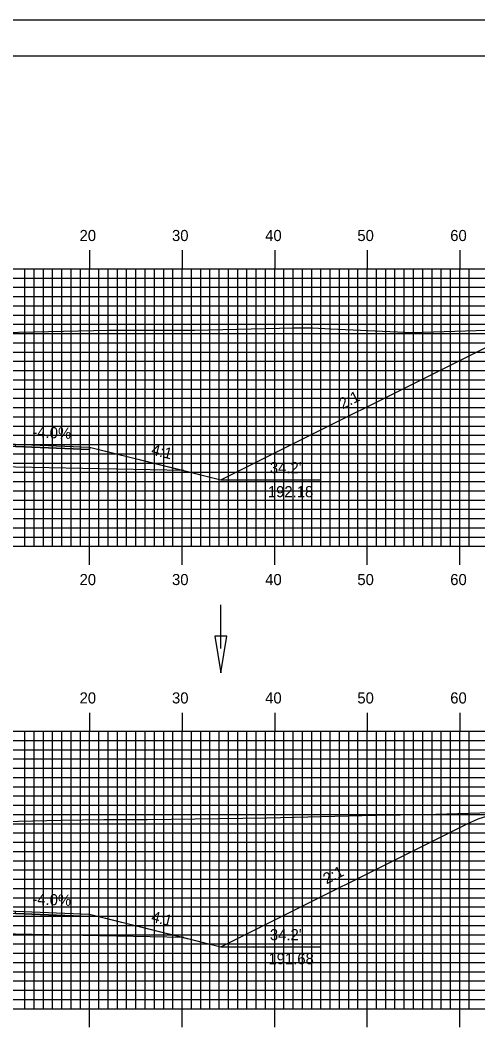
# Model space of a CAD drawing. Extents: x 1799568 to 1799912, y 442591 to 442811.
# Drawn here: x 1799746.5 to 1799796, y 442701.2 to 442810.5 of the extents above; entities that cross this region are included whole.
import ezdxf

# ---------------------------------------------------------------- set-up
doc = ezdxf.new("R2010")
doc.units = 0
for name, color, linetype in [('ANNOTATION', 7, 'Continuous'), ('BORDER', 7, 'Continuous'), ('D_Drainage_Ditch_Line', 7, 'Continuous'), ('D_Roadway_Centerline', 7, 'Continuous'), ('D_Roadway_Edge_Shoulder', 7, 'Continuous'), ('D_Roadway_SlopeLines', 7, 'Continuous'), ('D_Roadway_SubGrade', 7, 'Continuous'), ('H_V ANNOTATION', 7, 'Continuous'), ('MAJOR', 7, 'Continuous'), ('MINOR', 7, 'Continuous'), ('PDRAIN', 7, 'Continuous'), ('PLOT BOUNDARY', 7, 'Continuous'), ('S_Roadway_Centerline', 7, 'Continuous')]:
    doc.layers.add(name, color=color, linetype=linetype)

msp = doc.modelspace()

# ---------------------------------------------------------------- linework, layer by layer
at = {"layer": 'BORDER'}
msp.add_lwpolyline([(1799584.41, 442596.67), (1799904.41, 442596.67), (1799904.41, 442806.67), (1799584.41, 442806.67)], close=True, dxfattribs=at)
at = {"layer": 'D_Drainage_Ditch_Line'}
msp.add_line((1799768.18, 442742.63), (1799768.18, 442747.33), dxfattribs=at)
msp.add_lwpolyline([(1799768.84, 442743.94), (1799767.53, 442743.94), (1799768.18, 442740)], close=True, dxfattribs=at)
at = {"layer": 'D_Roadway_Centerline'}
for points in [[(1799669.45, 442775.1), (1799670.7, 442775.09), (1799671.95, 442774.91), (1799673.2, 442774.55), (1799674.45, 442774.02), (1799699.84, 442761.33), (1799703.84, 442762.33), (1799714.01, 442764.87), (1799722.01, 442765.19), (1799734.01, 442764.95), (1799746.01, 442764.71), (1799754.01, 442764.39), (1799764.18, 442761.85), (1799768.18, 442760.85), (1799798.21, 442775.86), (1799799.46, 442776.41), (1799800.71, 442776.8), (1799801.96, 442777.05), (1799803.21, 442777.14)], [(1799674.31, 442722.27), (1799675.56, 442722.22), (1799676.81, 442722.01), (1799678.06, 442721.63), (1799679.31, 442721.09), (1799699.84, 442710.83), (1799703.84, 442711.83), (1799714.01, 442714.37), (1799722.01, 442714.69), (1799734.01, 442714.45), (1799746.01, 442714.21), (1799754.01, 442713.89), (1799764.18, 442711.35), (1799768.18, 442710.35), (1799794.75, 442723.63), (1799796, 442724.18), (1799797.25, 442724.58), (1799798.5, 442724.84), (1799799.75, 442724.95)]]:
    msp.add_lwpolyline(points, dxfattribs=at)
at = {"layer": 'D_Roadway_Edge_Shoulder'}
for points in [[(1799746.01, 442764.71), (1799754.01, 442764.39), (1799754.01, 442764.14), (1799746.01, 442764.46)], [(1799746.01, 442714.21), (1799754.01, 442713.89), (1799754.01, 442713.64), (1799746.01, 442713.96)]]:
    msp.add_lwpolyline(points, close=True, dxfattribs=at)
at = {"layer": 'D_Roadway_SlopeLines'}
for points in [[(1799768.18, 442760.85), (1799798.21, 442775.86), (1799799.46, 442776.41), (1799800.71, 442776.8), (1799801.96, 442777.05), (1799803.21, 442777.14)], [(1799754.01, 442764.39), (1799768.18, 442760.85)], [(1799768.18, 442710.35), (1799794.75, 442723.63), (1799796, 442724.18), (1799797.25, 442724.58), (1799798.5, 442724.84), (1799799.75, 442724.95)], [(1799754.01, 442713.89), (1799768.18, 442710.35)]]:
    msp.add_lwpolyline(points, dxfattribs=at)
at = {"layer": 'D_Roadway_SubGrade'}
for points in [[(1799722.01, 442762.69), (1799703.84, 442762.33), (1799714.01, 442764.87), (1799714.01, 442764.62), (1799722.01, 442764.94), (1799734.01, 442764.7), (1799746.01, 442764.46), (1799754.01, 442764.14), (1799754.01, 442764.39), (1799764.18, 442761.85), (1799746.01, 442762.21), (1799734.01, 442762.45)], [(1799722.01, 442712.19), (1799703.84, 442711.83), (1799714.01, 442714.37), (1799714.01, 442714.12), (1799722.01, 442714.44), (1799734.01, 442714.2), (1799746.01, 442713.96), (1799754.01, 442713.64), (1799754.01, 442713.89), (1799764.18, 442711.35), (1799746.01, 442711.71), (1799734.01, 442711.95)]]:
    msp.add_lwpolyline(points, close=True, dxfattribs=at)
at = {"layer": 'MAJOR'}
for p, q in [((1799754.01, 442785.67), (1799754.01, 442783.67)), ((1799764.01, 442785.67), (1799764.01, 442783.67)), ((1799774.01, 442785.67), (1799774.01, 442783.67)), ((1799784.01, 442785.67), (1799784.01, 442783.67)), ((1799794.01, 442785.67), (1799794.01, 442783.67)), ((1799594.01, 442783.67), (1799874.01, 442783.67)), ((1799594.01, 442783.67), (1799874.01, 442783.67)), ((1799754.01, 442753.67), (1799754.01, 442783.67)), ((1799764.01, 442753.67), (1799764.01, 442783.67)), ((1799774.01, 442753.67), (1799774.01, 442783.67)), ((1799784.01, 442753.67), (1799784.01, 442783.67)), ((1799794.01, 442753.67), (1799794.01, 442783.67)), ((1799594.01, 442778.67), (1799874.01, 442778.67)), ((1799594.01, 442773.67), (1799874.01, 442773.67)), ((1799594.01, 442768.67), (1799874.01, 442768.67)), ((1799594.01, 442763.67), (1799874.01, 442763.67)), ((1799594.01, 442758.67), (1799874.01, 442758.67)), ((1799594.01, 442753.67), (1799874.01, 442753.67)), ((1799594.01, 442753.67), (1799874.01, 442753.67)), ((1799754.01, 442751.66), (1799754.01, 442753.67)), ((1799764.01, 442751.66), (1799764.01, 442753.67)), ((1799774.01, 442751.66), (1799774.01, 442753.67)), ((1799784.01, 442751.66), (1799784.01, 442753.67)), ((1799794.01, 442751.66), (1799794.01, 442753.67)), ((1799754.01, 442735.67), (1799754.01, 442733.67)), ((1799764.01, 442735.67), (1799764.01, 442733.67)), ((1799774.01, 442735.67), (1799774.01, 442733.67)), ((1799784.01, 442735.67), (1799784.01, 442733.67)), ((1799794.01, 442735.67), (1799794.01, 442733.67)), ((1799594.01, 442733.67), (1799874.01, 442733.67)), ((1799594.01, 442733.67), (1799874.01, 442733.67)), ((1799754.01, 442703.67), (1799754.01, 442733.67)), ((1799764.01, 442703.67), (1799764.01, 442733.67)), ((1799774.01, 442703.67), (1799774.01, 442733.67)), ((1799784.01, 442703.67), (1799784.01, 442733.67)), ((1799794.01, 442703.67), (1799794.01, 442733.67)), ((1799594.01, 442728.67), (1799874.01, 442728.67)), ((1799594.01, 442723.67), (1799874.01, 442723.67)), ((1799594.01, 442718.67), (1799874.01, 442718.67)), ((1799594.01, 442713.67), (1799874.01, 442713.67)), ((1799594.01, 442708.67), (1799874.01, 442708.67)), ((1799594.01, 442703.67), (1799874.01, 442703.67)), ((1799594.01, 442703.67), (1799874.01, 442703.67)), ((1799754.01, 442701.66), (1799754.01, 442703.67)), ((1799764.01, 442701.66), (1799764.01, 442703.67)), ((1799774.01, 442701.66), (1799774.01, 442703.67)), ((1799784.01, 442701.66), (1799784.01, 442703.67)), ((1799794.01, 442701.66), (1799794.01, 442703.67))]:
    msp.add_line(p, q, dxfattribs=at)
at = {"layer": 'MINOR'}
for p, q in [((1799747.01, 442753.67), (1799747.01, 442783.67)), ((1799748.01, 442753.67), (1799748.01, 442783.67)), ((1799749.01, 442753.67), (1799749.01, 442783.67)), ((1799750.01, 442753.67), (1799750.01, 442783.67)), ((1799751.01, 442753.67), (1799751.01, 442783.67)), ((1799752.01, 442753.67), (1799752.01, 442783.67)), ((1799753.01, 442753.67), (1799753.01, 442783.67)), ((1799755.01, 442753.67), (1799755.01, 442783.67)), ((1799756.01, 442753.67), (1799756.01, 442783.67)), ((1799757.01, 442753.67), (1799757.01, 442783.67)), ((1799758.01, 442753.67), (1799758.01, 442783.67)), ((1799759.01, 442753.67), (1799759.01, 442783.67)), ((1799760.01, 442753.67), (1799760.01, 442783.67)), ((1799761.01, 442753.67), (1799761.01, 442783.67)), ((1799762.01, 442753.67), (1799762.01, 442783.67)), ((1799763.01, 442753.67), (1799763.01, 442783.67)), ((1799765.01, 442753.67), (1799765.01, 442783.67)), ((1799766.01, 442753.67), (1799766.01, 442783.67)), ((1799767.01, 442753.67), (1799767.01, 442783.67)), ((1799768.01, 442753.67), (1799768.01, 442783.67)), ((1799769.01, 442753.67), (1799769.01, 442783.67)), ((1799770.01, 442753.67), (1799770.01, 442783.67)), ((1799771.01, 442753.67), (1799771.01, 442783.67)), ((1799772.01, 442753.67), (1799772.01, 442783.67)), ((1799773.01, 442753.67), (1799773.01, 442783.67)), ((1799775.01, 442753.67), (1799775.01, 442783.67)), ((1799776.01, 442753.67), (1799776.01, 442783.67)), ((1799777.01, 442753.67), (1799777.01, 442783.67)), ((1799778.01, 442753.67), (1799778.01, 442783.67)), ((1799779.01, 442753.67), (1799779.01, 442783.67)), ((1799780.01, 442753.67), (1799780.01, 442783.67)), ((1799781.01, 442753.67), (1799781.01, 442783.67)), ((1799782.01, 442753.67), (1799782.01, 442783.67)), ((1799783.01, 442753.67), (1799783.01, 442783.67)), ((1799785.01, 442753.67), (1799785.01, 442783.67)), ((1799786.01, 442753.67), (1799786.01, 442783.67)), ((1799787.01, 442753.67), (1799787.01, 442783.67)), ((1799788.01, 442753.67), (1799788.01, 442783.67)), ((1799789.01, 442753.67), (1799789.01, 442783.67)), ((1799790.01, 442753.67), (1799790.01, 442783.67)), ((1799791.01, 442753.67), (1799791.01, 442783.67)), ((1799792.01, 442753.67), (1799792.01, 442783.67)), ((1799793.01, 442753.67), (1799793.01, 442783.67)), ((1799795.01, 442753.67), (1799795.01, 442783.67)), ((1799594.01, 442782.67), (1799874.01, 442782.67)), ((1799594.01, 442781.67), (1799874.01, 442781.67)), ((1799594.01, 442780.67), (1799874.01, 442780.67)), ((1799594.01, 442779.67), (1799874.01, 442779.67)), ((1799594.01, 442777.67), (1799874.01, 442777.67)), ((1799594.01, 442776.67), (1799874.01, 442776.67)), ((1799594.01, 442775.67), (1799874.01, 442775.67)), ((1799594.01, 442774.67), (1799874.01, 442774.67)), ((1799594.01, 442772.67), (1799874.01, 442772.67)), ((1799594.01, 442771.67), (1799874.01, 442771.67)), ((1799594.01, 442770.67), (1799874.01, 442770.67)), ((1799594.01, 442769.67), (1799874.01, 442769.67)), ((1799594.01, 442767.67), (1799874.01, 442767.67)), ((1799594.01, 442766.67), (1799874.01, 442766.67)), ((1799594.01, 442765.67), (1799874.01, 442765.67)), ((1799594.01, 442764.67), (1799874.01, 442764.67)), ((1799594.01, 442762.67), (1799874.01, 442762.67)), ((1799594.01, 442761.67), (1799874.01, 442761.67)), ((1799594.01, 442760.67), (1799874.01, 442760.67)), ((1799594.01, 442759.67), (1799874.01, 442759.67)), ((1799594.01, 442757.67), (1799874.01, 442757.67)), ((1799594.01, 442756.67), (1799874.01, 442756.67)), ((1799594.01, 442755.67), (1799874.01, 442755.67)), ((1799594.01, 442754.67), (1799874.01, 442754.67)), ((1799747.01, 442703.67), (1799747.01, 442733.67)), ((1799748.01, 442703.67), (1799748.01, 442733.67)), ((1799749.01, 442703.67), (1799749.01, 442733.67)), ((1799750.01, 442703.67), (1799750.01, 442733.67)), ((1799751.01, 442703.67), (1799751.01, 442733.67)), ((1799752.01, 442703.67), (1799752.01, 442733.67)), ((1799753.01, 442703.67), (1799753.01, 442733.67)), ((1799755.01, 442703.67), (1799755.01, 442733.67)), ((1799756.01, 442703.67), (1799756.01, 442733.67)), ((1799757.01, 442703.67), (1799757.01, 442733.67)), ((1799758.01, 442703.67), (1799758.01, 442733.67)), ((1799759.01, 442703.67), (1799759.01, 442733.67)), ((1799760.01, 442703.67), (1799760.01, 442733.67)), ((1799761.01, 442703.67), (1799761.01, 442733.67)), ((1799762.01, 442703.67), (1799762.01, 442733.67)), ((1799763.01, 442703.67), (1799763.01, 442733.67)), ((1799765.01, 442703.67), (1799765.01, 442733.67)), ((1799766.01, 442703.67), (1799766.01, 442733.67)), ((1799767.01, 442703.67), (1799767.01, 442733.67)), ((1799768.01, 442703.67), (1799768.01, 442733.67)), ((1799769.01, 442703.67), (1799769.01, 442733.67)), ((1799770.01, 442703.67), (1799770.01, 442733.67)), ((1799771.01, 442703.67), (1799771.01, 442733.67)), ((1799772.01, 442703.67), (1799772.01, 442733.67)), ((1799773.01, 442703.67), (1799773.01, 442733.67)), ((1799775.01, 442703.67), (1799775.01, 442733.67)), ((1799776.01, 442703.67), (1799776.01, 442733.67)), ((1799777.01, 442703.67), (1799777.01, 442733.67)), ((1799778.01, 442703.67), (1799778.01, 442733.67)), ((1799779.01, 442703.67), (1799779.01, 442733.67)), ((1799780.01, 442703.67), (1799780.01, 442733.67)), ((1799781.01, 442703.67), (1799781.01, 442733.67)), ((1799782.01, 442703.67), (1799782.01, 442733.67)), ((1799783.01, 442703.67), (1799783.01, 442733.67)), ((1799785.01, 442703.67), (1799785.01, 442733.67)), ((1799786.01, 442703.67), (1799786.01, 442733.67)), ((1799787.01, 442703.67), (1799787.01, 442733.67)), ((1799788.01, 442703.67), (1799788.01, 442733.67)), ((1799789.01, 442703.67), (1799789.01, 442733.67)), ((1799790.01, 442703.67), (1799790.01, 442733.67)), ((1799791.01, 442703.67), (1799791.01, 442733.67)), ((1799792.01, 442703.67), (1799792.01, 442733.67)), ((1799793.01, 442703.67), (1799793.01, 442733.67)), ((1799795.01, 442703.67), (1799795.01, 442733.67)), ((1799594.01, 442732.67), (1799874.01, 442732.67)), ((1799594.01, 442731.67), (1799874.01, 442731.67)), ((1799594.01, 442730.67), (1799874.01, 442730.67)), ((1799594.01, 442729.67), (1799874.01, 442729.67)), ((1799594.01, 442727.67), (1799874.01, 442727.67)), ((1799594.01, 442726.67), (1799874.01, 442726.67)), ((1799594.01, 442725.67), (1799874.01, 442725.67)), ((1799594.01, 442724.67), (1799874.01, 442724.67)), ((1799594.01, 442722.67), (1799874.01, 442722.67)), ((1799594.01, 442721.67), (1799874.01, 442721.67)), ((1799594.01, 442720.67), (1799874.01, 442720.67)), ((1799594.01, 442719.67), (1799874.01, 442719.67)), ((1799594.01, 442717.67), (1799874.01, 442717.67)), ((1799594.01, 442716.67), (1799874.01, 442716.67)), ((1799594.01, 442715.67), (1799874.01, 442715.67)), ((1799594.01, 442714.67), (1799874.01, 442714.67)), ((1799594.01, 442712.67), (1799874.01, 442712.67)), ((1799594.01, 442711.67), (1799874.01, 442711.67)), ((1799594.01, 442710.67), (1799874.01, 442710.67)), ((1799594.01, 442709.67), (1799874.01, 442709.67)), ((1799594.01, 442707.67), (1799874.01, 442707.67)), ((1799594.01, 442706.67), (1799874.01, 442706.67)), ((1799594.01, 442705.67), (1799874.01, 442705.67)), ((1799594.01, 442704.67), (1799874.01, 442704.67))]:
    msp.add_line(p, q, dxfattribs=at)
at = {"layer": 'PDRAIN'}
for p, q in [((1799768.18, 442760.85), (1799778.95, 442760.85)), ((1799768.18, 442710.35), (1799778.95, 442710.35))]:
    msp.add_line(p, q, dxfattribs=at)
at = {"layer": 'PLOT BOUNDARY'}
msp.add_lwpolyline([(1799568.22, 442590.55), (1799908.22, 442590.55), (1799908.22, 442810.55), (1799568.22, 442810.55)], close=True, dxfattribs=at)
at = {"layer": 'S_Roadway_Centerline'}
for points in [[(1799594.01, 442772.87), (1799612.88, 442772.89), (1799616.92, 442772.95), (1799637.36, 442774.28), (1799638.29, 442774.36), (1799639.12, 442774.38), (1799660.98, 442774.53), (1799661.78, 442774.57), (1799673.01, 442775.34), (1799678.53, 442775.5), (1799695.85, 442775.53), (1799707.37, 442775.82), (1799709.4, 442775.86), (1799732.2, 442776.5), (1799733.54, 442776.55), (1799743.03, 442776.75), (1799756.05, 442777.02), (1799765.34, 442777.04), (1799776.04, 442777.28), (1799778.11, 442777.28), (1799780.07, 442777.19), (1799788.87, 442776.77), (1799799.24, 442777.09)], [(1799594.01, 442719.89), (1799595.64, 442719.95), (1799613.16, 442720.63), (1799618.33, 442720.65), (1799635.69, 442721.39), (1799641.86, 442721.73), (1799650.01, 442721.67), (1799659.41, 442721.95), (1799662.94, 442722.07), (1799666.11, 442722.03), (1799681, 442722.46), (1799689.09, 442722.87), (1799697.17, 442723.13), (1799714.49, 442723.04), (1799726.1, 442723.39), (1799731.09, 442723.58), (1799750.91, 442724.04), (1799755.54, 442724.14), (1799760.22, 442724.12), (1799773.17, 442724.3), (1799784.95, 442724.59), (1799790.22, 442724.67), (1799809.27, 442725.24)]]:
    msp.add_lwpolyline(points, dxfattribs=at)

# ---------------------------------------------------------------- texts
at = {"layer": 'ANNOTATION'}
for s, rotation, p in [('2:1', 26.5651, (1799781.34, 442768.46)), ('-4.0%', 357.7094, (1799747.8, 442765.44)), ('4:1', 345.9638, (1799760.6, 442763.6)), ('2:1', 26.5651, (1799779.61, 442717.1)), ('-4.0%', 357.7094, (1799747.8, 442714.94)), ('4:1', 345.9638, (1799760.6, 442713.1))]:
    msp.add_text(s, height=1.2, rotation=rotation, dxfattribs=at).set_placement(p)
for s, p in [("34.2'", (1799773.49, 442761.57)), ('192.18', (1799773.27, 442758.97)), ("34.2'", (1799773.49, 442711.07)), ('191.68', (1799773.33, 442708.47))]:
    msp.add_text(s, height=1.2, dxfattribs=at).set_placement(p)
at = {"layer": 'H_V ANNOTATION'}
for s, p in [('20', (1799752.92, 442786.67)), ('30', (1799762.91, 442786.67)), ('40', (1799772.98, 442786.67)), ('50', (1799782.94, 442786.67)), ('60', (1799792.98, 442786.67)), ('20', (1799752.92, 442749.47)), ('30', (1799762.91, 442749.47)), ('40', (1799772.98, 442749.47)), ('50', (1799782.94, 442749.47)), ('60', (1799792.98, 442749.47)), ('20', (1799752.92, 442736.67)), ('30', (1799762.91, 442736.67)), ('40', (1799772.98, 442736.67)), ('50', (1799782.94, 442736.67)), ('60', (1799792.98, 442736.67))]:
    msp.add_text(s, height=1.2, dxfattribs=at).set_placement(p)

doc.saveas('drawing.dxf')
